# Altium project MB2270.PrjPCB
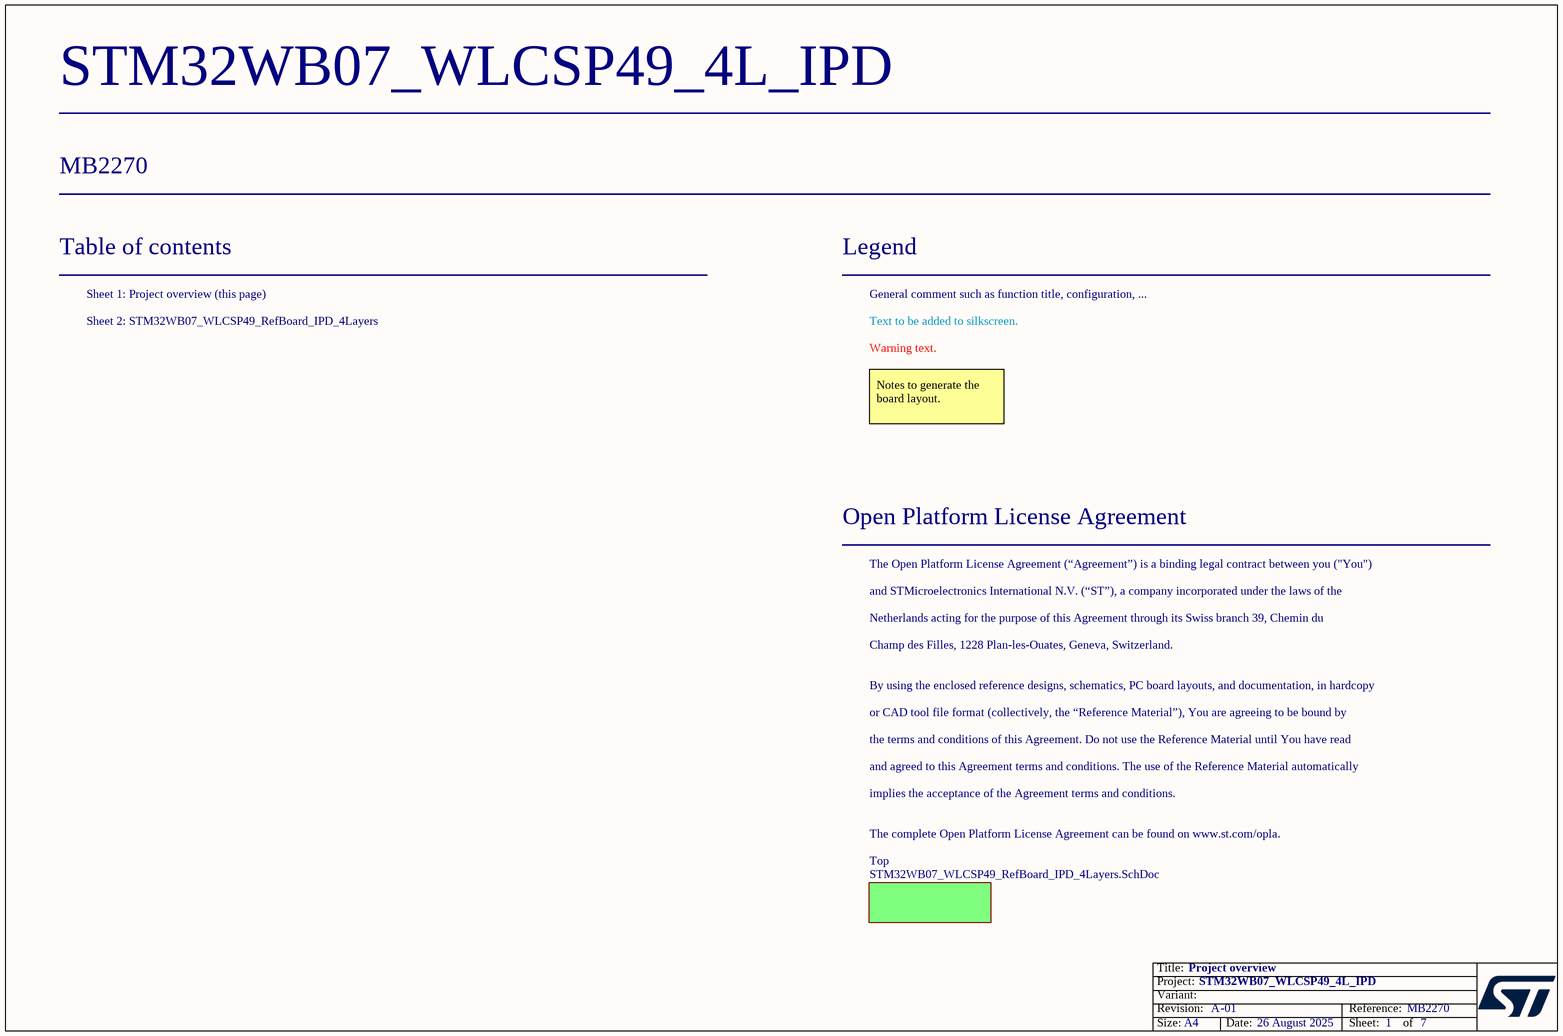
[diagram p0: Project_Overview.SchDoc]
Board_Assembly_Revision: 01; Board_Document_Date: 26 August 2025; Board_Name: STM32WB07_WLCSP49_4L_IPD; Board_PCB_Revision: A; Board_Reference: MB2270
2 sheets, 38 parts. Net scope: global (net labels, ports and power ports of the same name join across sheets).
Board file: MB2270.PcbDoc
Sheets:
  Project_Overview.SchDoc
    Top = STM32WB07_WLCSP49_RefBoard_IPD_4Layers.SchDoc

## Sheet Project_Overview.SchDoc: Project overview
size A4; Date: Not used; ApprovedBy: Not used; CheckedBy: Not used; Author: Not used; CompanyName: STMicroelectronics; DrawnBy: Not used; Engineer: Not used; Organization: Not used; Address1: Not used; Address2: Not used; Address3: Not used; Address4: Not used; DocumentNumber: Not used; Revision: Not used; SheetNumber: 1; SheetTotal: 7

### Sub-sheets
Top = STM32WB07_WLCSP49_RefBoard_IPD_4Layers.SchDoc: no entries

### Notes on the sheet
- Table of contents
- Sheet 1: Project overview (this page)
- Legend
- General comment such as function title, configuration, ...
- Sheet 2: STM32WB07_WLCSP49_RefBoard_IPD_4Layers
- Text to be added to silkscreen.
- Warning text.
- Notes to generate the board layout.
- Open Platform License Agreement
- The Open Platform License Agreement (“Agreement”) is a binding legal contract between you ("You")
- and STMicroelectronics International N.V. (“ST”), a company incorporated under the laws of the
- Netherlands acting for the purpose of this Agreement through its Swiss branch 39, Chemin du
- Champ des Filles, 1228 Plan-les-Ouates, Geneva, Switzerland.
- By using the enclosed reference designs, schematics, PC board layouts, and documentation, in hardcopy
- or CAD tool file format (collectively, the “Reference Material”), You are agreeing to be bound by
- the terms and conditions of this Agreement. Do not use the Reference Material until You have read
- and agreed to this Agreement terms and conditions. The use of the Reference Material automatically
- implies the acceptance of the Agreement terms and conditions.
- The complete Open Platform License Agreement can be found on www.st.com/opla.

## Sheet STM32WB07_WLCSP49_RefBoard_IPD_4Layers.SchDoc: STM32WB07_WLCSP49_SMPS
size A3; Date: Not used; ApprovedBy: Not used; CheckedBy: Not used; Author: Not used; CompanyName: STMicroelectronics; DrawnBy: Not used; Engineer: Not used; Organization: Not used; Address1: Not used; Address2: Not used; Address3: Not used; Address4: Not used; DocumentNumber: Not used; Revision: Not used; SheetNumber: 2; SheetTotal: 2
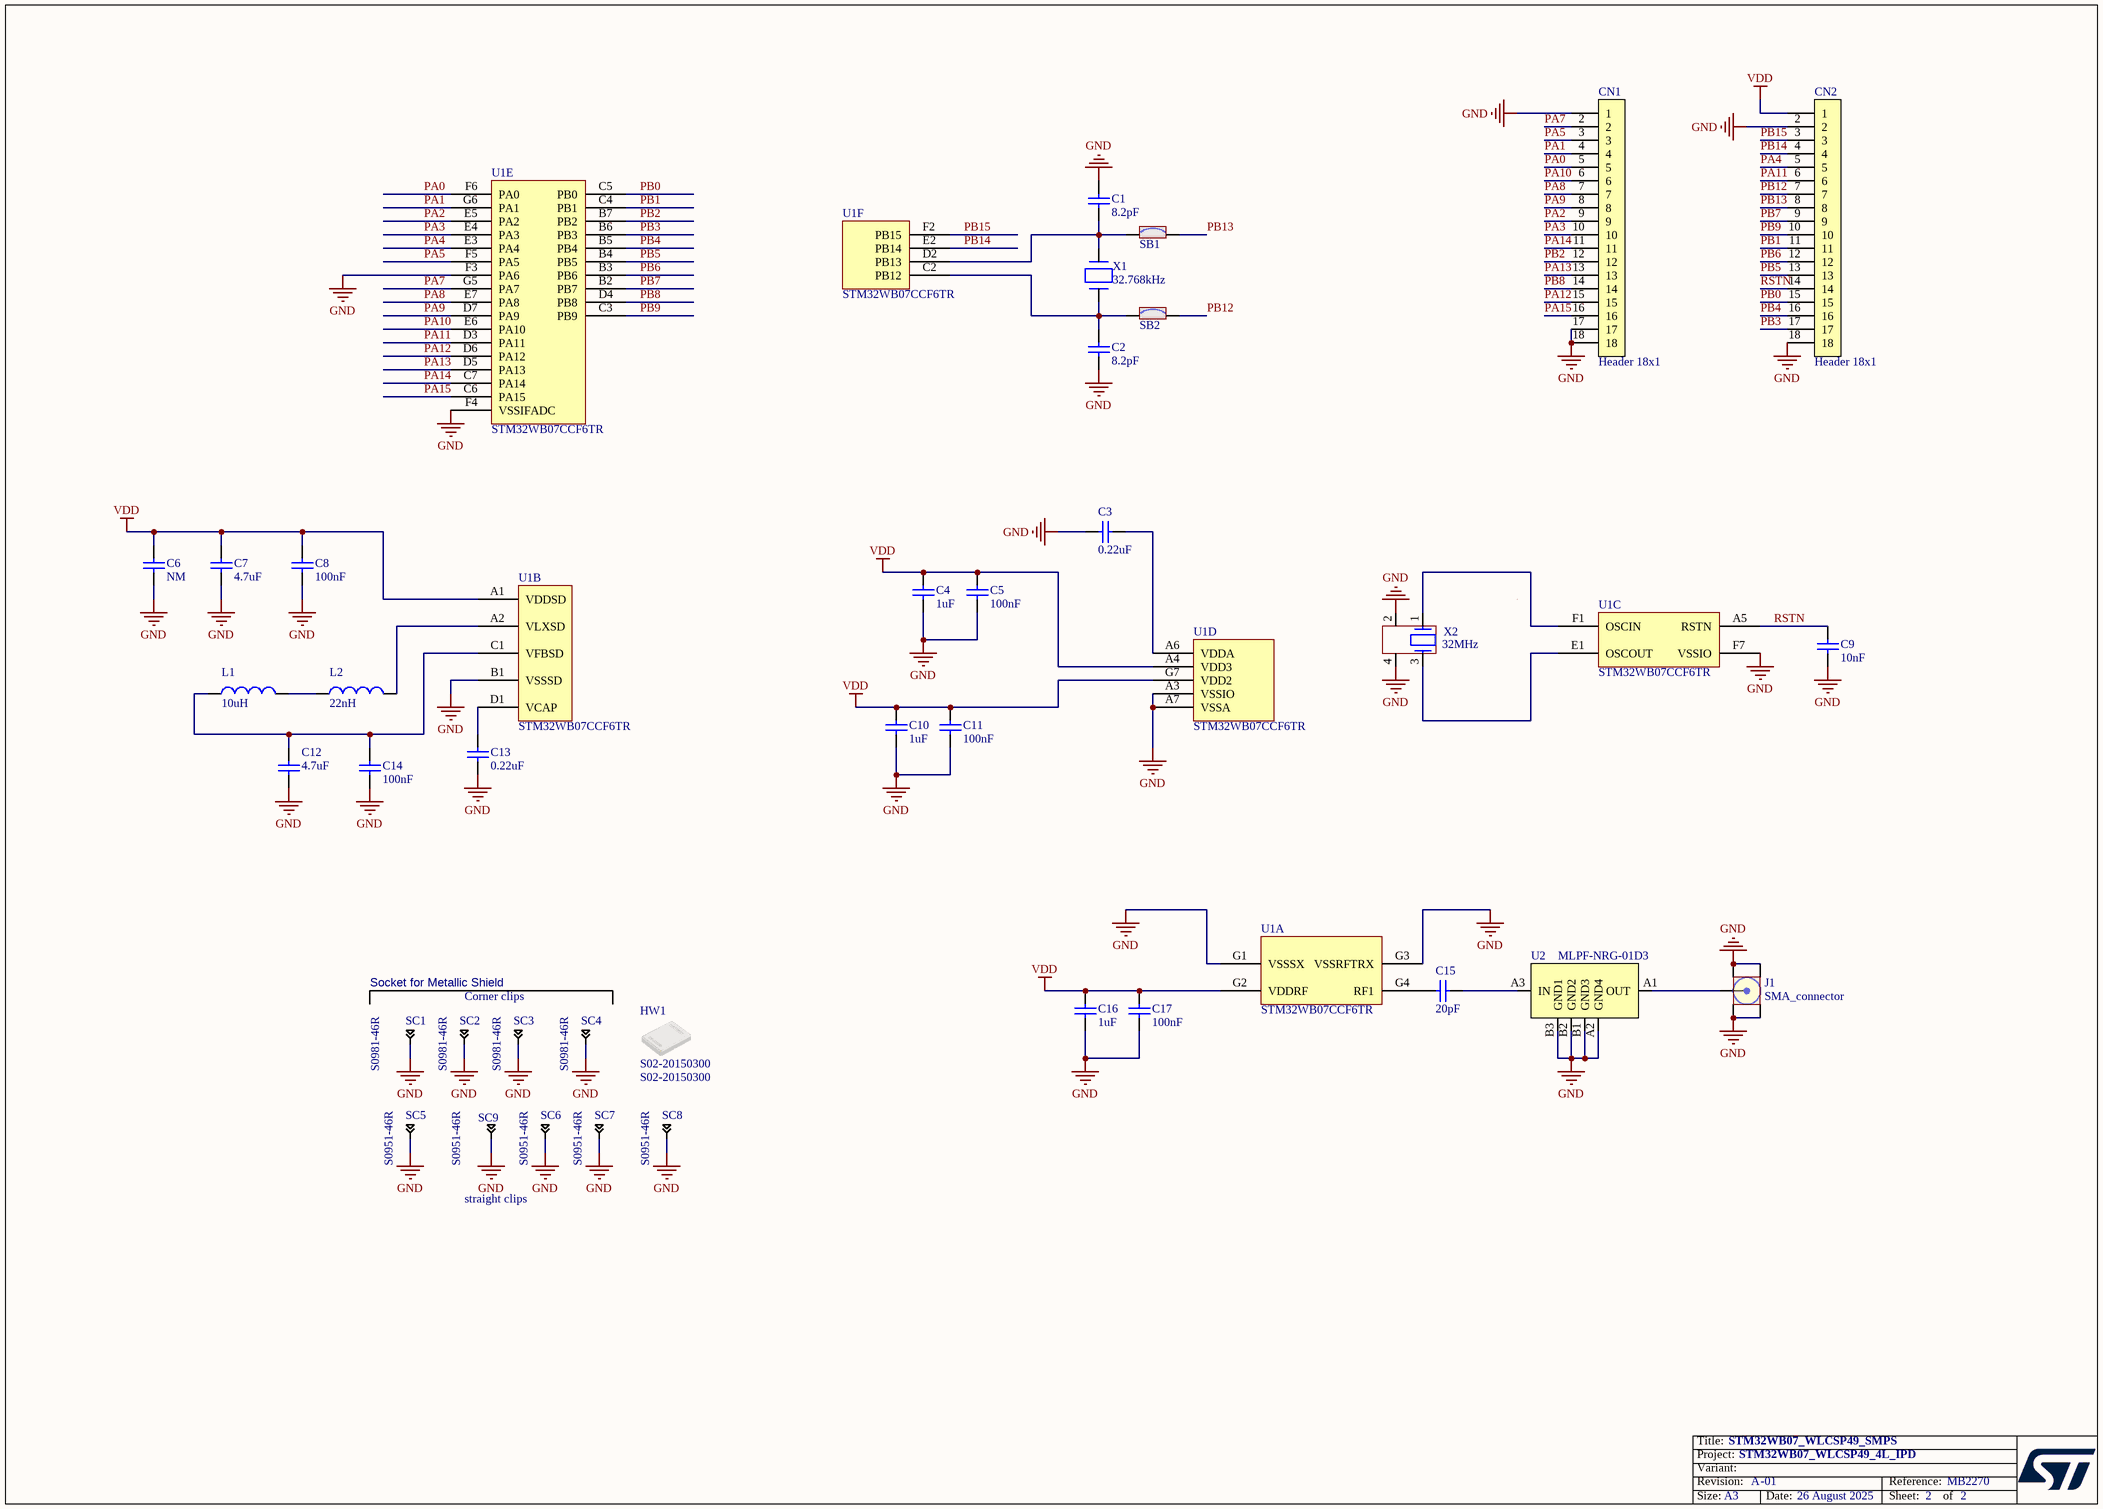
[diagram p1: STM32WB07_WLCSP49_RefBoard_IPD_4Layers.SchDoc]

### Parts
C1  value 8.2pF  [C0402]  (hidden comment: Capacitor)
C2  value 8.2pF  [C0402]  (hidden comment: Capacitor)
C3  value 0.22uF  [C0402]  (hidden comment: Capacitor)
C4  value 1uF  [C0402]  (hidden comment: Capacitor)
C5  value 100nF  [C0201_H0P3]  (hidden comment: Capacitor)
C6  value NM  [C0402]  (hidden comment: Capacitor)
C7  value 4.7uF  [C0402]  (hidden comment: Capacitor)
C8  value 100nF  [C0201_H0P3]  (hidden comment: Capacitor)
C9  value 10nF  [C0402]  (hidden comment: Capacitor)
C10  value 1uF  [C0402]  (hidden comment: Capacitor)
C11  value 100nF  [C0201_H0P3]  (hidden comment: Capacitor)
C12  value 4.7uF  [C0402]  (hidden comment: Capacitor)
C13  value 0.22uF  [C0402]  (hidden comment: Capacitor)
C14  value 100nF  [C0201_H0P3]  (hidden comment: Capacitor)
C15  value 20pF  [20p_capacitor_SMD_0201]  (hidden comment: Capacitor)
C16  value 1uF  [C0402]  (hidden comment: Capacitor)
C17  value 100nF  [C0201_H0P3]  (hidden comment: Capacitor)
CN1  Header 18x1  [CON_SAMTEC_TSW-118-07-X-S]
CN2  Header 18x1  [CON_SAMTEC_TSW-118-07-X-S]
HW1  S02-20150300  [SHIELD_HARWIN_S02-20150300_15X20_H3]
J1  SMA_connector  [SMA_AMPHENOL_132415]
L1  value 10uH  [IND_0805_MURATA_LQM21]  (hidden comment: Inductor)
L2  value 22nH  [C0402]  (hidden comment: Inductor)
SB1  SB_ON  [SOLDER-BRIDGE_R0402-0R]  (value not drawn)
SB2  SB_ON  [SOLDER-BRIDGE_R0402-0R]  (value not drawn)
SC1  value S0981-46R  [CLIP_HARWIN_S0981-46R]  (hidden comment: Shield-clip_S0951-46R)
SC2  value S0981-46R  [CLIP_HARWIN_S0981-46R]  (hidden comment: Shield-clip_S0951-46R)
SC3  value S0981-46R  [CLIP_HARWIN_S0981-46R]  (hidden comment: Shield-clip_S0951-46R)
SC4  value S0981-46R  [CLIP_HARWIN_S0981-46R]  (hidden comment: Shield-clip_S0951-46R)
SC5  value S0951-46R  [CLIP_HARWIN_S0951-46R]  (hidden comment: Shield-clip_S0951-46R)
SC6  value S0951-46R  [CLIP_HARWIN_S0951-46R]  (hidden comment: Shield-clip_S0951-46R)
SC7  value S0951-46R  [CLIP_HARWIN_S0951-46R]  (hidden comment: Shield-clip_S0951-46R)
SC8  value S0951-46R  [CLIP_HARWIN_S0951-46R]  (hidden comment: Shield-clip_S0951-46R)
SC9  value S0951-46R  [CLIP_HARWIN_S0951-46R]  (hidden comment: Shield-clip_S0951-46R)
U1  STM32WB07CCF6TR  [STM32WB07_WLCSP49]  (parts A,B,C,D,E,F of 6)
U2  value MLPF-NRG-01D3  [ICC_CSPG_6BUMPS_1X1P60_P050-P0577]  (hidden comment: MLPF-WB55-01E3)
X1  value 32.768kHz  [CRY_NX2012SA_2P]  (hidden comment: XTAL_2_PINS)
X2  value 32MHz  [CRY_NX2016SA_4P]  (hidden comment: XTAL_4_PINS)

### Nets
GND: C1.2 C2.1 C3.2 C4.1 C5.1 C6.1 C7.1 C8.1 C9.2 C10.1 C11.1 C12.1 C13.2 C14.1 C16.1 C17.1 CN1.1 CN1.17 CN1.18 CN2.2 CN2.18 J1.2(Y) SC1.1 SC2.1 SC3.1 SC4.1 SC5.1 SC6.1 SC7.1 SC8.1 SC9.1 U1.A3(VSSIO) U1.A7(VSSA) U1.B1(VSSSD) U1.F3(PA6) U1.F4(VSSIFADC) U1.F7(VSSIO) U1.G1(VSSSX) U1.G3(VSSRFTRX) U2.A2(GND4) U2.B1(GND3) U2.B2(GND2) U2.B3(GND1) X2.2 X2.4
VDD: C4.2 C5.2 C6.2 C7.2 C8.2 C10.2 C11.2 C16.2 C17.2 CN2.1 U1.A1(VDDSD) U1.A4(VDD3) U1.G2(VDDRF) U1.G7(VDD2)
PA0: CN1.5 U1.F6(PA0)
PA1: CN1.4 U1.G6(PA1)
PA2: CN1.9 U1.E5(PA2)
PA3: CN1.10 U1.E4(PA3)
PA4: CN2.5 U1.E3(PA4)
PA5: CN1.3 U1.F5(PA5)
PA7: CN1.2 U1.G5(PA7)
PA8: CN1.7 U1.E7(PA8)
PA9: CN1.8 U1.D7(PA9)
PA10: CN1.6 U1.E6(PA10)
PA11: CN2.6 U1.D3(PA11)
PA12: CN1.15 U1.D6(PA12)
PA13: CN1.13 U1.D5(PA13)
PA14: CN1.11 U1.C7(PA14)
PA15: CN1.16 U1.C6(PA15)
PB0: CN2.15 U1.C5(PB0)
PB1: CN2.11 U1.C4(PB1)
PB2: CN1.12 U1.B7(PB2)
PB3: CN2.17 U1.B6(PB3)
PB4: CN2.16 U1.B5(PB4)
PB5: CN2.13 U1.B4(PB5)
PB6: CN2.12 U1.B3(PB6)
PB7: CN2.9 U1.B2(PB7)
PB8: CN1.14 U1.D4(PB8)
PB9: CN2.10 U1.C3(PB9)
PB12: CN2.7 SB2.1
PB13: CN2.8 SB1.1
PB14: CN2.4 U1.E2(PB14)
PB15: CN2.3 U1.F2(PB15)
RSTN: C9.1 CN2.14 U1.A5(RSTN)
NetC1_1: C1.1 SB1.2 U1.D2(PB13) X1.1(X1)
NetC2_2: C2.2 SB2.2 U1.C2(PB12) X1.2(X2)
NetC3_1: C3.1 U1.A6(VDDA)
NetC12_2: C12.2 C14.2 L1.1 U1.C1(VFBSD)
NetC13_1: C13.1 U1.D1(VCAP)
NetC15_1: C15.1 U1.G4(RF1)
NetC15_2: C15.2 U2.A3(IN)
NetJ1_1: J1.1(X) U2.A1(OUT)
NetL1_2: L1.2 L2.1
NetL2_2: L2.2 U1.A2(VLXSD)
NetU1_E1: U1.E1(OSCOUT) X2.3
NetU1_F1: U1.F1(OSCIN) X2.1

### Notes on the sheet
- Socket for Metallic Shield
- Corner clips
- straight clips

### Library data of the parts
C1 C2 = MCD-03429: Capacitor, MLCC, 8.2 pF, NPO, COG, 50V, +/-0.1pF, 0402, T=0.5mm; Part_Preference: Recommended; Manufacturer: MURATA; Manufacturer_Part_Number: GJM1555C1H8R2BB01D; Order_Code_RS: 185-3272; Component_Country_Of_Origin: Japan, Singapore; ShowFields: YES; ID: 5545
C3 C13 = MCD-03483: Capacitor, MLCC, 0.22uF, X5R, 6.3V, +/-10%, 0402, T=0.5mm; Part_Preference: Recommended; Manufacturer: YAGEO; Manufacturer_Part_Number: CC0402KRX5R5BB224; Order_Code_RS: 3369131; ShowFields: YES; ID: 5599; Component_Country_Of_Origin: China
C4 C10 C16 = MCD-03432: Capacitor, MLCC, 1uF, X7R, 6.3V,+/- 10%, 0402, T=0.5mm; Part_Preference: Recommended; Manufacturer: MURATA; Manufacturer_Part_Number: GRM155R70J105KA12; Order_Code_RS: 113-8711; ShowFields: YES; ID: 5548; Component_Country_Of_Origin: China, Japan, Philippines, Singapore
C5 C8 C11 C14 C17 = MCD-01535: Capacitor, MLCC,100nF, 10V, X5R, +/-10%, 0201, T=0.3mm; Part_Preference: Recommended; Manufacturer: MURATA; Manufacturer_Part_Number: GRM033R61A104KE15; Order_Code_RS: 790-2742; Component_Country_Of_Origin: Japan; ShowFields: YES; ID: 3635
C6 C7 C12 = MCD-03431: Capacitor, MLCC, 4.7uF, X5R, 10V, +/-20%, 0402, T=0.5mm; Part_Preference: Recommended; Manufacturer: MURATA; Manufacturer_Part_Number: GRM155R61A475MEAAD; Order_Code_RS: 172-6870; ShowFields: YES; ID: 5547; Component_Country_Of_Origin: China, Japan, Philippines, Singapore
C9 = MCD-00011: Capacitor, MLCC, 10nF, 16V, X7R, +/-10%, 0402, T=0.5mm; Part_Preference: Recommended; Manufacturer: YAGEO; Manufacturer_Part_Number: CC0402KRX7R7BB103; Order_Code_RS: 3019275; Component_Country_Of_Origin: China; ShowFields: YES; ID: 2469
C15 = MCD-03543: Capacitor, MLCC, 20pF, 25V, COG, +/-2%, 0201, T=0.3mm; Part_Preference: Recommended; Manufacturer: MURATA; Manufacturer_Part_Number: GJM0335C1E200GB01; ShowFields: YES; ID: 5659; Component_Country_Of_Origin: Japan, Singapore
CN1 CN2 = MCD-01897: Header, 18x1, 2.54mm, VR, TH, T=5.84mm/8.38mm; Part_Type: Connector; Part_Preference: Recommended; Manufacturer: SAMTEC; Manufacturer_Part_Number: TSW-118-07-L-S; Order_Code_RS: 767-1141; Component_Country_Of_Origin: China, Costa Rica, Malaysia, United States, Vietnam; ShowFields: YES; ID: 3997
HW1 = MCD-03126: RFI shield can, 20x15x3mm; Part_Type: Misc; Part_Preference: Recommended; Manufacturer: HARWIN; Order_Code_RS: 161-3687; Component_Country_Of_Origin: UK°; ShowFields: YES; ID: 5242
J1 = SMA_connector: Rf Connector, Sma End Launch Recept Jack For .032" Pcb / Individual Bag; Manufacturer: Amphenol Connex; Manufacturer Part Number: 132415; Note: Replacement with compatible component is forbidden.
L1 = MCD-03438: Inductor, MLCC, 10uH, +/-20%, 300mA, 845mR, 0805, T=1.45mm; Part_Preference: Recommended; Manufacturer: MURATA; Manufacturer_Part_Number: LQM21DN100M70L; Order_Code_RS: NA; ShowFields: YES; ID: 5554; Component_Country_Of_Origin: Japan
L2 = MCD-03439: Inductor, MLCC, 22nH, +/-2%, 350mA, 0.58R, 0402, T=1.45mm; Part_Preference: Recommended; Manufacturer: MURATA; Manufacturer_Part_Number: LQG15HN22NG02D; Order_Code_RS: 3354168; ShowFields: YES; ID: 5555; Component_Country_Of_Origin: Japan
SB1 SB2 = MCD-01618: Resistor, 0R, SB0402, 5%, 0.063W; Part_Preference: Recommended; Manufacturer: YAGEO; Manufacturer_Part_Number: RC0402JR-070RL; Order_Code_RS: 618-5804; Component_Country_Of_Origin: China; ShowFields: YES; ID: 3718
SC1-SC4 = MCD-02164: Shield clip Harwin S0981-46R to fix RF shielded cavity; Part_Type: Mechanical; Part_Preference: Recommended; Order_Code_RS: 161-3702; Component_Country_Of_Origin: South Korea; ShowFields: YES; ID: 4264
SC5-SC9 = MCD-01587: RFI shield clip mini TIN SMD; Part_Type: Mechanical; Part_Preference: Recommended; Manufacturer: HARWIN; Component_Country_Of_Origin: South Korea; ShowFields: YES; ID: 3687
U1 = STM32WB07_WLCSP49: IC, Bluetooth Low Energy wireless SoC, WLCSP49; Manufacturer: STMICROELECTRONICS
U2 = MCD-03490: 2.4 GHz low pass filter matched to BLUENRG-LP-LPS; Part_Type: IC; Part_Preference: Recommended; Manufacturer: STMICROELECTRONICS; Component_Country_Of_Origin: China; ShowFields: YES; ID: 5606; Note: Provided by St
X1 = MCD-01445: Crystal, 32.768kHz, 7pF, +/-20ppm, 80K, 2.05x1.2mm; BMS_Part_Number: 9157043; Part_Type: Crystal_Osc; Part_Preference: Recommended; Manufacturer: NDK; Manufacturer_Part_Number: NX2012SE 32.768kHz EXS00A-MU01259; Component_Country_Of_Origin: Unknown; ShowFields: YES; ID: 3545
X2 = MCD-01446: Crystal, 32MHz, 8pF, +/-10ppm, 60R, 2x1.6mm; BMS_Part_Number: 9157042; Part_Type: Crystal_Osc; Part_Preference: Recommended; Manufacturer: NDK; Manufacturer_Part_Number: NX2016SA-32MHZ-EXS00A-CS06654; Component_Country_Of_Origin: Unknown; ShowFields: YES; ID: 3546

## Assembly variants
Variant A: not fitted C6 CN1 CN2 SB1 SB2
